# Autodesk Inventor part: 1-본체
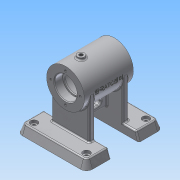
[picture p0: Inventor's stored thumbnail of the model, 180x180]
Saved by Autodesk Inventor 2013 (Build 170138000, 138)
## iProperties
Created: 2016-07
Part Number: 1-본체
Material: 알루미늄 6061
Document SubType Name: Modeling
Designer: Administrator
Density: 2.71 g/cm^3
Mass: 498.89 g
Surface Area: 543.451 cm^2
Volume: 184.092 cm^3
Author: Administrator
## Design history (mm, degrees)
sketch "스케치1"
  geometry: L1 (-50, 55)-(50, 55); L2 (50, 55)-(50, 20); L3 (50, 20)-(-50, 20); L4 (-50, 20)-(-50, 55); 1 further point
  constraints: 8 end point, 2 parallel, 1 horizontal, 1 perpendicular
  dimensions: "d0" = 100 distance of L1.start L1.end; "d2" = 35 distance of L3.end L1.start; "d3" = 55 distance from line of point (0, 0) L1; "d4" = 50 distance from line of point (0, 0) L4
extrude "돌출1" new body sketch "스케치1" distance "d5" = 12; taper "d6" = 0 deg
node "작업 평면1"
sketch "스케치2"
  geometry: L1 (-35, 70)-(35, 70); L2 (-35, 70)-(35, 70); L3 (35, 70)-(35, 97); L4 (35, 97)-(-35, 97); L5 (-35, 97)-(-35, 70); 1 further point
  constraints: 10 end point, 2 horizontal, 2 parallel, 1 perpendicular
  dimensions: "d8" = 70 distance from line of point (0, 0) L1; "d9" = 70 distance of L1.start L1.end; "d10" = 35 horizontal distance of point (0, 0) L1.start; "d11" = 54 diameter of L4 L1
revolve "회전1" sketch "스케치2" stored, may be unused: angle "d12" = 90 deg
sketch "스케치3"
  geometry: L1 (0, -12)-(100, -12) reference; L2 (77, -70)-(23, -70); L3 (23, -70)-(23, -12); L4 (23, -12)-(77, -12); L5 (77, -12)-(77, -70); 2 further points
  constraints: 8 end point, 2 midpoint, 2 parallel, 1 horizontal, 1 perpendicular
  dimensions: "d13" = 54 distance between parallel lines of L3 L5; "d15" = 27 distance from line of point (50, 0) L5; "d16" = 58 distance of L2.end L3.end
extrude "돌출2" join sketch "스케치3" distance "d17" = 8; taper "d18" = 0 deg
sketch "스케치4"
  geometry: L1 (-22.876, 44.652)-(22.814, 44.652) reference; L2 (22.814, 44.652)-(22.814, 22) reference; L3 (22.814, 22)-(-22.876, 22); L4 (-22.876, 22)-(-22.876, 44.652) reference; L5 (-35, 43)-(35, 43) reference; 1 further point
  constraints: 8 end point, 2 horizontal, 2 parallel, 2 vertical, 1 perpendicular
  dimensions: "d21" = 21 distance between parallel lines of L3 L5
extrude "돌출3" join sketch "스케치4" stored distance "d22" = 8; taper "d23" = 0 deg
sketch "스케치5"
  geometry: L1 (-22, -20)-(-22, 20) reference; L2 (-35.5, -8)-(-35.5, 8); L3 (-28.5, -8)-(-28.5, 8); L4 (0, 55)-(0, 20) reference; L5 (-35.5, 0)-(-28.5, 0); L6 (-43, -35)-(-97, -35) reference; A1 r 3.5 centre (-32, -8) between (-35.5, -8) and (-28.5, -8); A2 r 3.5 centre (-32, 8) between (-28.5, 8) and (-35.5, 8); 1 further point
  constraints: 6 end point, 4 point on circle, 4 tangent, 2 centre point, 2 midpoint, 1 parallel, 1 vertical
  dimensions: "d24" = 3.5 radius of A2; "d26" = 32 distance from line of L4 A2.centre; "d27" = 16 distance of A2.centre A1.centre; "d28" = 35 distance between parallel lines of L5 L6
extrude "돌출4" cut sketch "스케치5" stored distance "d29" = 0; taper "d30" = 0 deg
node "작업 평면2"
sketch "스케치6"
  geometry: L1 (27, -35)-(-27, -35) reference; C1 r 5 at (0, -13); 1 further point
  constraints: 1 centre point, 1 vertical alignment
  dimensions: "d32" = 10 diameter of C1; "d34" = 22 distance from line of C1.centre L1
extrude "돌출5" join sketch "스케치6" stored distance "d35" = 8; taper "d36" = 0 deg
sketch "스케치10"
  geometry: L1 (-35, 70)-(35, 70); L2 (-35, 43)-(-35, 97) reference; L3 (20, 0)-(55, 0) reference; L4 (-35, 70)-(-23, 70); L5 (-23, 70)-(-23, 86); L6 (-23, 86)-(-35, 86); L7 (-35, 86)-(-35, 70); L8 (-23, 70)-(-21, 70); L9 (-21, 70)-(-21, 84); L10 (-21, 84)-(-23, 84); L11 (-23, 84)-(-23, 70); L12 (-21, 70)-(21, 70); L13 (21, 70)-(21, 92); L14 (21, 92)-(-21, 92); L15 (-21, 92)-(-21, 70); L16 (21, 70)-(23, 70); L17 (23, 70)-(23, 84); L18 (23, 84)-(21, 84); L19 (21, 84)-(21, 70); L20 (23, 70)-(35, 70); L21 (35, 70)-(35, 86); L22 (35, 86)-(23, 86); L23 (23, 86)-(23, 70); 1 further point
  constraints: 42 end point, 10 parallel, 6 horizontal, 5 perpendicular, 1 midpoint
  dimensions: "d48" = 70 distance of L1.end L1.start; "d50" = 70 distance between parallel lines of L3 L1; "d51" = 32 diameter of L6 L1; "d52" = 12 distance between parallel lines of L5 L2; "d53" = 28 diameter of L10 L1; "d54" = 2 distance between parallel lines of L15 L5; "d55" = 44 diameter of L14 L1; "d56" = 42 distance between parallel lines of L19 L15; "d57" = 28 diameter of L18 L1; "d58" = 2 distance between parallel lines of L17 L19; "d60" = 32 diameter of L22 L1
revolve "회전2" sketch "스케치10" stored, may be unused: angle "d61" = 90 deg
chamfer "모따기2" distance "d62" = 1; stored, may be unused: second distance "d63" = 2, angle "d64" = 45 deg
fillet "모깎기1" dims "d65" = 0.3
node "작업 평면3"
sketch "스케치11"
  geometry: L1 (0, 70)-(15.898, 44.559); L2 (0, 70)-(0, 58.695); C1 r 27 at (0, 70) reference; 1 further point
  constraints: 4 end point, 1 vertical
  dimensions: "d69" = 32 deg angle of L2 L1; "d70" = 30 distance of L1.start L1.end
node "작업 평면4"
sketch "스케치12"
  geometry: C1 r 6 at (0, 0); 2 further points
  constraints: 1 centre point, 1 coincident
  dimensions: "d71" = 12 diameter of C1
extrude "돌출7" join sketch "스케치12" stored distance "d73" = 42; taper "d74" = 0 deg
sketch "스케치13"
  geometry: C1 r 27 at (0, 0) reference; 2 further points
  constraints: 1 vertical alignment
  dimensions: "d75" = 21 distance of C1.centre point (0, -21)
hole "구멍1" sketch "스케치13" at (0, -21) diameter "d76" = 3.242; stored, may be unused: countersink angle "d80" = 90 deg, drill point angle "d82" = 120 deg; dims "d77" = 8, "d78" = 4, "d79" = 2, "d81" = 10
hole "구멍2" diameter "d88" = 5.188; stored, may be unused: countersink angle "d92" = 90 deg, drill point angle "d94" = 120 deg; dims "d86" = 10, "d87" = 10, "d89" = 8, "d90" = 4, "d91" = 2, "d93" = 10
hole "구멍3" diameter "d97" = 5.188; stored, may be unused: countersink angle "d101" = 90 deg, drill point angle "d103" = 120 deg; dims "d95" = 10, "d96" = 10, "d98" = 8, "d99" = 4, "d100" = 2, "d102" = 10
node "작업 평면5"
sketch "스케치14"
  geometry: L1 (-35, 43)-(-35, 97) reference; L2 (-35, 97)-(35, 97) reference; 2 further points
  constraints: 1 other
  dimensions: "d105" = 35 distance from line of point (0, 70) L1; "d106" = 27 distance from line of point (0, 70) L2
feature "엠보싱1" sketch "스케치14" dims "d107" = 0.5, "d108" = 0
sketch "스케치15"
  geometry: L1 (-23, 8)-(-23, -27) reference; L2 (-23, -27)-(77, -27) reference; 5 further points
  dimensions: "d119" = 12.5 distance from line of L1 point (-10.5, -14.5); "d120" = 12.5 distance from line of L2 point (-10.5, -14.5)
hole "구멍4" sketch "스케치15" at (-10.5, -14.5) diameter "d121" = 6; stored, may be unused: countersink angle "d125" = 90 deg, drill point angle "d127" = 120 deg; dims "d122" = 8, "d123" = 10, "d124" = 4, "d126" = 10
feature "면 기울기3" dims angle "d128" = 20 deg
feature "면 기울기4" dims angle "d129" = 20 deg
fillet "모깎기6" dims "d130" = 10, "d131" = 5
fillet "모깎기7" dims "d132" = 10, "d133" = 5
fillet "모깎기8" dims "d134" = 10, "d135" = 5
fillet "모깎기9" dims "d136" = 10, "d137" = 5
fillet "모깎기10" dims "d138" = 2
fillet "모깎기11" dims "d139" = 2
fillet "모깎기12" dims "d140" = 2
fillet "모깎기15" dims "d143" = 2
fillet "모깎기16" dims "d144" = 2
fillet "모깎기17" dims "d145" = 2
fillet "모깎기18" dims "d146" = 2
fillet "모깎기21" dims "d149" = 2
fillet "모깎기24" dims "d152" = 2
fillet "모깎기25" dims "d153" = 2
fillet "모깎기26" dims "d154" = 2
fillet "모깎기27" dims "d157" = 2
node "솔리드1"
mirror "대칭1"
mirror "대칭2"
pattern_circular "원형 패턴1" dims angle "d84" = 360 deg
mirror "대칭3"
mirror "대칭4"
mirror "대칭5"
other parameters: "d7" = 0, "d68" = 0
